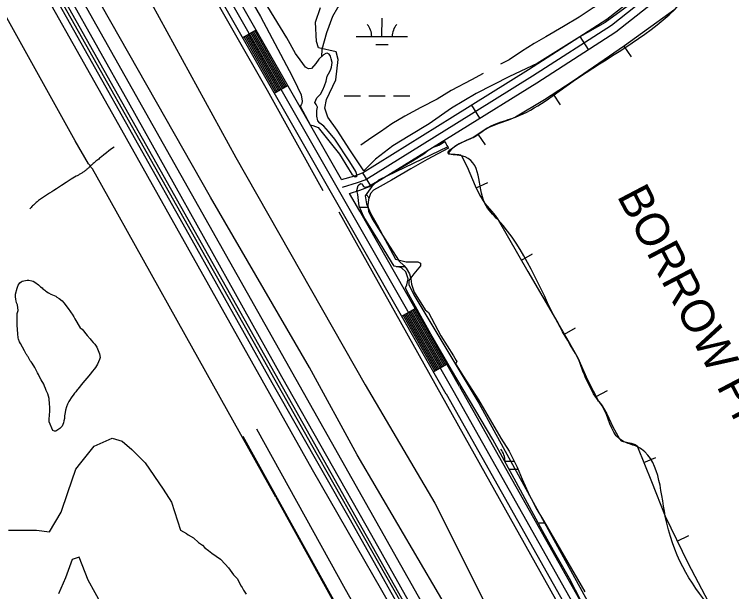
# Model space of a CAD drawing. Extents: x 3187622 to 3225504, y 800805 to 826213.
# Drawn here: x 3193075 to 3194473, y 822799 to 823924 of the extents above; entities that cross this region are included whole.
import ezdxf

# ---------------------------------------------------------------- set-up
doc = ezdxf.new("R2010")
doc.units = 0
for name, color, linetype in [('V-BORW-IDEN', 7, 'Continuous'), ('V-BORW-LINE', 7, 'Continuous'), ('V-LEVE-TOET', 7, 'Continuous'), ('V-RAIL-TRAK', 7, 'Continuous'), ('V-ROAD-CNTR', 7, 'Continuous'), ('V-SITE-VEGE', 7, 'Continuous'), ('V-SURV-LINE', 7, 'Continuous'), ('V-TOPO-SHOR', 7, 'Continuous'), ('V-WETL-SWMP', 7, 'Continuous')]:
    doc.layers.add(name, color=color, linetype=linetype)

msp = doc.modelspace()

# ---------------------------------------------------------------- linework, layer by layer
at = {"layer": 'V-BORW-LINE'}
for p, q in [((3194262.7, 823862), (3194276.9, 823841.4)), ((3194124.8, 823768.5), (3194138.4, 823747.5)), ((3193978.4, 823690.5), (3193992.4, 823669.9)), ((3193974.9, 823585.9), (3193997.5, 823596.6)), ((3194063, 823445.1), (3194084.6, 823457.6)), ((3194146.6, 823300.9), (3194168.2, 823313.5)), ((3194208.7, 823179.2), (3194230.8, 823191)), ((3194301.5, 823051.1), (3194324.6, 823060.5)), ((3194366.5, 822897.8), (3194389, 822908.7))]:
    msp.add_line(p, q, dxfattribs=at)
for points in [[(3194361.6, 823933.7), (3194263.6, 823862.7), (3194163.8, 823793.7), (3194108.1, 823757.7), (3194051.2, 823723.8), (3194037.9, 823717.6), (3194016.9, 823710.6), (3193996.4, 823702.4), (3193982.7, 823693.4), (3193969, 823684.2), (3193955.5, 823678), (3193941.7, 823672), (3193935.2, 823668), (3193926.4, 823660.6), (3193920.4, 823653.8), (3193920.1, 823653), (3193921, 823652.1), (3193933.9, 823651.9), (3193941.4, 823651.2), (3193944.3, 823650.2), (3193946.2, 823648.6), (3193957.6, 823626.9), (3193972.9, 823590.2), (3193981.5, 823572.1), (3193991.8, 823555.6), (3194005.1, 823539.8), (3194011.7, 823531.9), (3194017.5, 823523.4), (3194075.7, 823423.3), (3194133.8, 823323.1), (3194153.6, 823288.9), (3194173.2, 823254.5)], [(3194173.2, 823254.5), (3194191.4, 823211.7), (3194213.4, 823170.5), (3194216.8, 823165.7), (3194220.4, 823161), (3194229.5, 823145.4), (3194241, 823120.5), (3194253.9, 823096.6), (3194257.2, 823093.3), (3194261, 823091.5), (3194277.1, 823088.2), (3194284.4, 823085.8), (3194287.2, 823083.8), (3194289.3, 823081), (3194316.7, 823013.5), (3194343.3, 822945.9), (3194387, 822855.3), (3194433.8, 822766.2)]]:
    msp.add_lwpolyline(points, dxfattribs=at)
for points in [[(3194173.2, 823254.5), (3194133.8, 823323.1), (3194017.5, 823523.4), (3193991.8, 823555.6), (3193946.2, 823648.6), (3193920.4, 823653.8), (3193941.7, 823672), (3193969, 823684.2), (3193996.4, 823702.4), (3194051.2, 823723.8), (3194163.8, 823793.7), (3194361.6, 823933.7), (3194445, 824013.4), (3194502.9, 824036.7), (3194535.5, 824045.1), (3194547.6, 824055.8), (3194568.2, 824150.6), (3194657.5, 824394.2), (3194681.2, 824428.3)], [(3194746.7, 824428.2), (3194770.2, 824392.5), (3194839.9, 824358.9), (3194843.7, 824354.2), (3194822.9, 824352.6), (3194805.6, 824354.5), (3194783.8, 824344), (3194808, 824310.6), (3194860.9, 824111.5), (3194890.3, 824049), (3194919.9, 824022.8), (3194936.8, 823993.7), (3194967.5, 823945.1), (3194990.2, 823878.8), (3195044.4, 823786.8), (3195063.9, 823718), (3195053.2, 823688.8), (3195056.3, 823616.2), (3195008.6, 823396.2), (3194962.2, 823257.3), (3194949.6, 823254.7), (3194916.1, 823270.5), (3194892.6, 823394.4), (3194818.7, 823675.4), (3194764.8, 823725), (3194732.1, 823768.5), (3194627.7, 823861.2), (3194598.2, 823922.8), (3194572.9, 824011.1), (3194544.8, 824024.5), (3194532.2, 824018.4), (3194535.7, 823972.4), (3194544.3, 823935.6), (3194590.6, 823765.3), (3194640.4, 823657.8), (3194680.8, 823529.9), (3194719.1, 823459), (3194750.6, 823333.9), (3194793.9, 823142.5), (3194772.9, 823135.8), (3194752.4, 823099.7), (3194748.5, 823050.4), (3194776.1, 822932.3), (3194811.1, 822874.8), (3194830.8, 822797.1), (3194831.1, 822768.9), (3194796.7, 822656), (3194757.4, 822452), (3194745.4, 822448.1), (3194718.1, 822363.5), (3194698.9, 822349.8), (3194685.3, 822355.9), (3194657.8, 822398.5), (3194530.3, 822600.2), (3194494, 822692.8), (3194433.8, 822766.2), (3194343.3, 822945.9), (3194289.3, 823081), (3194253.9, 823096.6), (3194220.4, 823161), (3194213.4, 823170.5), (3194173.2, 823254.5)]]:
    msp.add_spline(points, degree=3, dxfattribs=at)
at = {"layer": 'V-LEVE-TOET'}
for points in [[(3193584.3, 822982.9), (3193407.8, 823299.3), (3193245.4, 823590.8), (3193227.2, 823623), (3193224.5, 823626.5), (3193223, 823629.3), (3193219.8, 823632.7), (3193193.4, 823677.9), (3193057.2, 823923.2), (3192861.4, 824271.3), (3192771.4, 824432.2)], [(3193069, 824431.6), (3193107.9, 824362.3), (3193312.3, 824000.4), (3193506.6, 823644.9), (3193758.4, 823202.4), (3193894.5, 822971.4)], [(3193584.3, 822982.9), (3193715.2, 822746.5), (3193715.3, 822746.3)], [(3193894.5, 822971.4), (3194028.2, 822704.5), (3194448.5, 821917.6)]]:
    msp.add_lwpolyline(points, dxfattribs=at)
at = {"layer": 'V-RAIL-TRAK'}
for points in [[(3193727.3, 822943), (3193577.7, 823206), (3193415.9, 823494.6), (3193219.9, 823842.7), (3193027.5, 824182.9), (3192887.4, 824431.9)], [(3194238.4, 822033.7), (3194009.1, 822443.2), (3193835.4, 822751.2), (3193727.3, 822943)]]:
    msp.add_lwpolyline(points, dxfattribs=at)
at = {"layer": 'V-ROAD-CNTR'}
for p, q in [((3193520, 823879), (3193546.1, 823893.9)), ((3194177, 823880.7), (3194193.2, 823855.4)), ((3193582, 823770.4), (3193608.1, 823785.3)), ((3193965.8, 823747.4), (3193981.6, 823721.9)), ((3193753.5, 823615.3), (3193769.3, 823589.9)), ((3193829.8, 823336.2), (3193855.9, 823351.1)), ((3193891.8, 823227.6), (3193917.8, 823242.5))]:
    msp.add_line(p, q, dxfattribs=at)
for points in [[(3193712.7, 823602), (3193738.4, 823609.7), (3193753.5, 823615.3), (3193928.5, 823724.2), (3194076.7, 823816.3), (3194229.7, 823914.5), (3194342.1, 824003.7), (3194404.7, 824048.8), (3194435.1, 824077.7), (3194479.6, 824135.2), (3194522.3, 824198.5), (3194552.2, 824257.2), (3194580, 824328.4), (3194616.3, 824418.1), (3194627.3, 824438.2)], [(3192892.8, 824434.6), (3193654.2, 823085.5)], [(3193916.6, 823184.2), (3193721.8, 823525.6), (3193306.3, 824253.5), (3193204.7, 824433.9)], [(3193222, 824433.9), (3193319.3, 824260.9), (3193734.8, 823533), (3193929.6, 823191.6)], [(3193712.7, 823602), (3193332.4, 824268.3), (3193239.2, 824433.9)], [(3194640.4, 824431), (3194629.9, 824411.7), (3194594, 824322.8), (3194565.9, 824251), (3194535.2, 824190.9), (3194491.7, 824126.4), (3194446.3, 824067.6), (3194414.3, 824037.3), (3194351.1, 823991.7), (3194238.4, 823902.3), (3194084.7, 823803.6), (3193936.4, 823711.5), (3193760.1, 823601.8), (3193743.1, 823595.5), (3193714.1, 823586.8)], [(3193728, 823575.3), (3193747.9, 823581.3), (3193766.8, 823588.3), (3193944.4, 823698.7), (3194092.7, 823790.9), (3194247.2, 823890.1), (3194360.2, 823979.8), (3194423.9, 824025.7), (3194457.4, 824057.5), (3194503.9, 824117.6), (3194548.1, 824183.3), (3194579.6, 824244.8), (3194607.9, 824317.3), (3194643.5, 824405.2), (3194653.6, 824423.8)], [(3193605.5, 823783.8), (3193543.5, 823892.4)], [(3193584.6, 823771.9), (3193522.7, 823880.5)], [(3193587.2, 823773.4), (3193525.3, 823882)], [(3193589.8, 823774.9), (3193527.9, 823883.5)], [(3193592.4, 823776.4), (3193530.5, 823884.9)], [(3193595, 823777.9), (3193533.1, 823886.4)], [(3193597.6, 823779.4), (3193535.7, 823887.9)], [(3193600.3, 823780.8), (3193538.3, 823889.4)], [(3193602.9, 823782.3), (3193540.9, 823890.9)], [(3193942.6, 823199), (3193747.9, 823540.4), (3193728, 823575.3)], [(3193912.6, 823239.5), (3193850.7, 823348.1)], [(3193915.2, 823241), (3193853.3, 823349.6)], [(3193894.4, 823229.1), (3193832.5, 823337.7)], [(3193897, 823230.6), (3193835.1, 823339.2)], [(3193899.6, 823232.1), (3193837.7, 823340.6)], [(3193902.2, 823233.6), (3193840.3, 823342.1)], [(3193904.8, 823235), (3193842.9, 823343.6)], [(3193907.4, 823236.5), (3193845.5, 823345.1)], [(3193910, 823238), (3193848.1, 823346.6)], [(3193942.7, 823199), (3195097.4, 821147.5)], [(3193916.5, 823184.3), (3195071.3, 821132.7)], [(3193929.6, 823191.6), (3195084.4, 821140.1)], [(3193546.7, 823116.4), (3193719.6, 822803.7), (3193783.2, 822690.8), (3193839.5, 822561.1), (3193931.2, 822385.2), (3194075.1, 822116.1), (3194127.2, 822033.7), (3194185.2, 821977.8), (3194639.7, 821147.1), (3195029.5, 820446.4), (3195072.9, 820348.7), (3195192.1, 820158.7), (3195238.4, 820041.1), (3195343.7, 819857.8), (3195584.5, 819427.5)], [(3193520.4, 823101.8), (3193693.4, 822789.1), (3193756.3, 822677.4), (3193812.4, 822548.2), (3193904.7, 822371.2), (3194049.2, 822101), (3194103.8, 822014.6), (3194161.1, 821959.4), (3194613.5, 821132.6), (3195002.6, 820433), (3195046.3, 820334.6), (3195165.2, 820145.1), (3195211.3, 820028), (3195317.6, 819843), (3195558.5, 819412.5)], [(3193654.2, 823085.5), (3194393.6, 821781.9), (3194932.5, 820818.5), (3195643.8, 819559.4), (3196039.6, 818863.6), (3196103.7, 818747.1), (3196200.1, 818577.4), (3196283.3, 818430.9), (3196415.9, 818198), (3196513.3, 818033.2), (3196633.1, 817833.5), (3197048.3, 817166.1), (3197473.1, 816486.2), (3198091.5, 815496.5), (3198625.8, 814645.6), (3198678.1, 814561.9), (3198728.8, 814484.2), (3198769.6, 814407.5), (3198909.8, 814179.8), (3198995, 814024.9)]]:
    msp.add_lwpolyline(points, dxfattribs=at)
at = {"layer": 'V-SITE-VEGE'}
for p, q in [((3193230.4, 823082.5), (3193265.7, 823098.5)), ((3193265.7, 823098.5), (3193285, 823092.1)), ((3193204.8, 823050.4), (3193230.4, 823082.5)), ((3193285, 823092.1), (3193304.3, 823076.1)), ((3193304.3, 823076.1), (3193329.9, 823050.4)), ((3193195.1, 823037.5), (3193204.8, 823050.4)), ((3193329.9, 823050.4), (3193365.2, 822999)), ((3193179.1, 822992.6), (3193195.1, 823037.5)), ((3193365.2, 822999), (3193381.3, 822973.3)), ((3193166.3, 822954.1), (3193179.1, 822992.6)), ((3193381.3, 822973.3), (3193399, 822918.7)), ((3193143.8, 822915.5), (3193166.3, 822954.1)), ((3193063.6, 822918.7), (3193082.8, 822918.7)), ((3193082.8, 822918.7), (3193118.1, 822918.7)), ((3193118.1, 822918.7), (3193143.8, 822915.5)), ((3193399, 822918.7), (3193404.4, 822915.5)), ((3193404.4, 822915.5), (3193410.7, 822912.2)), ((3193410.7, 822912.2), (3193413.8, 822909.8)), ((3193413.8, 822909.8), (3193423.9, 822904.1)), ((3193423.9, 822904.1), (3193434, 822895.2)), ((3193434, 822895.2), (3193441.8, 822889.6)), ((3193441.8, 822889.6), (3193446.5, 822884.8)), ((3193446.5, 822884.8), (3193453.5, 822879.1)), ((3193453.5, 822879.1), (3193459.7, 822874.3)), ((3193459.7, 822874.3), (3193476.8, 822862.1)), ((3193188, 822861.7), (3193174.6, 822826)), ((3193201.4, 822866.2), (3193188, 822861.7)), ((3193219.3, 822821.5), (3193201.4, 822866.2)), ((3193476.8, 822862.1), (3193486.1, 822852.5)), ((3193486.1, 822852.5), (3193492.3, 822845.3)), ((3193492.3, 822845.3), (3193502.3, 822831.7)), ((3193502.3, 822831.7), (3193509.3, 822824.5)), ((3193174.6, 822826), (3193161.2, 822794.7)), ((3193246.1, 822772.4), (3193219.3, 822821.5)), ((3193509.3, 822824.5), (3193516.9, 822810.1)), ((3193516.9, 822810.1), (3193519.2, 822806.9)), ((3193519.2, 822806.9), (3193521.5, 822802.2)), ((3193521.5, 822802.2), (3193526.9, 822794.2))]:
    msp.add_line(p, q, dxfattribs=at)
for points in [[(3193216.1, 823215.1), (3193212.4, 823210.3), (3193208.4, 823205.9), (3193199.1, 823193.7), (3193197.4, 823192.1), (3193195, 823188.5), (3193192.2, 823185.7), (3193189.7, 823182), (3193186.9, 823178.8), (3193181.6, 823169.9), (3193178.8, 823164.2), (3193176.7, 823159.4), (3193175.1, 823152.5), (3193173.9, 823148.1), (3193173.1, 823141.6), (3193172.6, 823136.3), (3193171.4, 823131.9), (3193171, 823127.8), (3193169.8, 823124.6), (3193168.2, 823121.4), (3193164.1, 823117.3), (3193160.1, 823114.5), (3193158, 823112.9), (3193156, 823111.7), (3193153.2, 823112.1), (3193149.9, 823113.3), (3193143.1, 823129.9), (3193143.1, 823135.2), (3193144.3, 823150.5), (3193144.4, 823159.4), (3193144, 823164.3), (3193142.8, 823175.6), (3193140.4, 823184.5), (3193137.5, 823191.4), (3193135.9, 823194.7), (3193133.9, 823199.5), (3193132.7, 823203.2), (3193127.5, 823211.7), (3193124.2, 823217.7), (3193122.2, 823222.2), (3193120.6, 823225.4), (3193117, 823231.9), (3193115, 823236), (3193109.7, 823244.1), (3193108.1, 823246.9), (3193106.1, 823248.9), (3193102.1, 823256.6), (3193100.8, 823258.3), (3193099.6, 823260.3), (3193098.4, 823261.9), (3193094.8, 823268.4), (3193087.1, 823282.6), (3193085.1, 823285.8), (3193083.1, 823291.1), (3193082.7, 823293.9), (3193081.9, 823301.2), (3193080.7, 823318.2), (3193080.7, 823329.9), (3193080.4, 823339.2), (3193080.8, 823341.2), (3193082.8, 823346.9), (3193081.2, 823357.8), (3193079.6, 823361.9), (3193078.8, 823365.5), (3193078, 823368.4), (3193077.2, 823374), (3193077.2, 823378.5), (3193080.9, 823390.6), (3193082.9, 823396.3), (3193084.9, 823399.1), (3193086.1, 823401.1), (3193088.6, 823403.1), (3193090.6, 823404.4), (3193099.9, 823406), (3193103.5, 823406), (3193109.2, 823405.1), (3193111.6, 823403.9), (3193115.3, 823401.9), (3193122.1, 823397), (3193126.2, 823393.4), (3193129.4, 823390.9), (3193131, 823389.3), (3193134.3, 823386.5), (3193136.3, 823384.8), (3193141.9, 823381.2), (3193146, 823378.8), (3193156.1, 823374.7), (3193158.1, 823373.1), (3193162.2, 823370.6), (3193168.2, 823365.8), (3193171.4, 823362.1), (3193180.3, 823350.8), (3193184.4, 823344.7), (3193185.6, 823342.7), (3193188, 823339.8), (3193190.8, 823334.6), (3193193.2, 823330.9), (3193203.7, 823313.5), (3193207, 823310.3), (3193217.1, 823298.5), (3193222.7, 823291.6)], [(3193222.7, 823291.6), (3193223.9, 823289.6), (3193228.8, 823284.7), (3193232, 823281.1), (3193235.6, 823275.8), (3193241.3, 823262.4), (3193242.1, 823255.6), (3193241.2, 823251.5), (3193239.2, 823246.7), (3193237.2, 823242.6), (3193233.5, 823235.8), (3193224.6, 823225.7), (3193223.4, 823223.6), (3193216.1, 823215.1)]]:
    msp.add_lwpolyline(points, dxfattribs=at)
at = {"layer": 'V-SURV-LINE'}
for points in [[(3193965.1, 822546.1), (3192901.9, 824431.9)], [(3192936.4, 824431.8), (3193991.3, 822560.8)]]:
    msp.add_lwpolyline(points, dxfattribs=at)
at = {"layer": 'V-TOPO-SHOR'}
for points in [[(3196669.7, 817789), (3196420.1, 818211.1), (3196348, 818329.5), (3196021.1, 818916.4), (3195920.7, 819106.9), (3195681.3, 819521.3), (3195459.9, 819917.7), (3195341.5, 820128.8), (3194986.3, 820754.3), (3194837, 821019.4), (3194610.5, 821418.4), (3194502.4, 821616.6), (3194445.8, 821717), (3194196.1, 822162.3), (3194075.1, 822368.2), (3193771.4, 822908.7), (3193596.3, 823217.6), (3193297.8, 823753), (3193179.4, 823964.1), (3192906.5, 824437.7)], [(3193189.6, 824437.7), (3193568, 823776.2), (3193676.1, 823580.6)], [(3192870.5, 824432.6), (3193272, 823719.6), (3193655.5, 823037.4), (3194095.7, 822270.4), (3194281, 821935.8), (3194281, 821921.4), (3194293.9, 821912.6), (3194523, 821505.9), (3194839.6, 820947.3), (3195012.1, 820643.6), (3195336.4, 820069.6), (3195480.5, 819812.2), (3195732.8, 819366.9)], [(3195107.3, 820738.8), (3195071.3, 820751.7), (3194754.7, 821292.3), (3194566.8, 821621.7), (3194288.8, 822113.4), (3194059.7, 822525.2), (3193743.1, 823065.8), (3193650.4, 823235.6), (3193457.3, 823567.7), (3193228.3, 823971.8), (3192963.1, 824435.1)], [(3193648.1, 823817.8), (3193642.1, 823821.2), (3193632.2, 823835.7), (3193622.7, 823847.9), (3193605.7, 823878.1), (3193569.1, 823938.7), (3193523.1, 824018), (3193465.9, 824122.3), (3193374.4, 824282.2), (3193290, 824431.1)], [(3193463.5, 824077.5), (3193554.4, 823920), (3193616.7, 823803.4), (3193627.1, 823782.1), (3193634.2, 823767.1), (3193636, 823755.2), (3193635.3, 823750.5), (3193633.7, 823747.5), (3193631.7, 823744.9), (3193651.7, 823708.9), (3193656.4, 823707.3), (3193667.1, 823703.8), (3193708.3, 823651.4), (3193726.1, 823623), (3193732.7, 823612.9), (3193738.9, 823607.4), (3193741.8, 823608.3), (3193742.9, 823609.6), (3193740.5, 823617.8), (3193728.7, 823636.8), (3193699.7, 823680.9), (3193687.2, 823695.7), (3193678.1, 823706.1), (3193670.5, 823711.8), (3193666.5, 823716.8), (3193664.4, 823725.6), (3193664.2, 823736.8), (3193666, 823743), (3193662.9, 823748.5), (3193660.5, 823752.4), (3193664.6, 823761.7), (3193671.4, 823768.7), (3193676.3, 823777.1), (3193679.4, 823784.7), (3193682.7, 823794), (3193684.3, 823803.9), (3193689.5, 823812.8), (3193691.8, 823817.5), (3193693.3, 823821.4), (3193694.3, 823830.4), (3193692.7, 823837.2), (3193691.1, 823842.6), (3193688.8, 823846.5), (3193684.9, 823848.4), (3193681.8, 823848.1), (3193677.6, 823845.5), (3193668.1, 823836.8), (3193662.4, 823828.2), (3193654.1, 823818.7), (3193648.1, 823817.8)], [(3193674.1, 823841.6), (3193675.1, 823856.1), (3193683.7, 823889), (3193695.5, 823920.6), (3193705.4, 823937.3), (3193717.7, 823954.1), (3193723.3, 823971.2), (3193735.2, 823990.1), (3193748.9, 824002), (3193760.1, 824016.6)], [(3194271, 823986.6), (3194246.8, 823966.2), (3194225, 823949), (3194203, 823936.5), (3194175.7, 823918.6), (3194144.8, 823900.2), (3194110.8, 823880.3), (3194087.8, 823867), (3194063, 823851.8)], [(3194063, 823851.8), (3194039.2, 823835.7), (3194022.2, 823826.7)], [(3193988.3, 823808.8), (3193965.5, 823796.8), (3193926.1, 823775.4), (3193899, 823758.8), (3193867.1, 823742.7), (3193835.8, 823725.4), (3193810.3, 823710.5), (3193788.5, 823695), (3193771.8, 823684.3), (3193750, 823669.3)], [(3193269.4, 823665.5), (3193264.4, 823661.9), (3193259.4, 823658.2), (3193254.5, 823654.5), (3193249.7, 823650.6), (3193244.9, 823646.7), (3193243.1, 823645.2), (3193243.1, 823645.2), (3193241.3, 823643.7), (3193239.5, 823642.2), (3193237.7, 823640.7), (3193235.9, 823639.3), (3193234.1, 823637.8), (3193232.3, 823636.3), (3193230.5, 823634.8), (3193228.7, 823633.2), (3193227, 823631.7), (3193225.2, 823630.2), (3193223.5, 823628.7), (3193223.4, 823628.6), (3193223.4, 823628.6), (3193222.3, 823627.5), (3193221.2, 823626.4), (3193220.1, 823625.3), (3193219, 823624.3), (3193217.8, 823623.3), (3193216.7, 823622.2), (3193215.5, 823621.2), (3193214.3, 823620.3), (3193213.1, 823619.3), (3193211.8, 823618.4), (3193210.6, 823617.5), (3193209.3, 823616.6), (3193208.1, 823615.7), (3193206.8, 823614.9), (3193205.5, 823614), (3193204.1, 823613.2), (3193202.8, 823612.5), (3193201.5, 823611.7), (3193200.1, 823611), (3193198.7, 823610.3), (3193197.3, 823609.6), (3193195.9, 823608.9), (3193195.7, 823608.8), (3193195.7, 823608.8), (3193186, 823602.7), (3193176.4, 823596.6), (3193166.8, 823590.4), (3193157.2, 823584.1), (3193152.2, 823580.8), (3193148.1, 823578.3), (3193144, 823575.8), (3193139.9, 823573.2), (3193135.8, 823570.6), (3193131.8, 823567.9), (3193127.9, 823565.1), (3193124.1, 823562.5), (3193124.1, 823562.5), (3193122.5, 823561.3), (3193121, 823560.1), (3193119.5, 823558.8), (3193118, 823557.6), (3193116.5, 823556.3), (3193115, 823554.9), (3193113.6, 823553.6), (3193112.2, 823552.2), (3193110.8, 823550.8), (3193109.5, 823549.4), (3193108.1, 823547.9), (3193106.8, 823546.5), (3193105.7, 823545.2)], [(3193919.5, 823665.7), (3193784.3, 823601.2), (3193771.4, 823588.3), (3193758.5, 823570.3), (3193761.1, 823554.8), (3193768.8, 823536.8), (3193781.7, 823513.6), (3193817.7, 823446.7), (3193838.3, 823441.6), (3193848.6, 823441.6), (3193861.5, 823441.6), (3193866.6, 823439), (3193866.6, 823433.9), (3193853.7, 823418.4), (3193843.5, 823405.5), (3193843.5, 823397.8), (3193853.7, 823377.2), (3193979.9, 823166.2), (3194268.2, 822641), (3194458.6, 822311.6), (3194777.8, 821742.7), (3194960.6, 821415.8), (3195056.3, 821245.3)], [(3193707, 823539.4), (3193961.9, 823083.8), (3194227, 822610.2), (3194435.5, 822249.8), (3194790.7, 821608.9), (3194893.7, 821433.8), (3195158.8, 820973.1)]]:
    msp.add_lwpolyline(points, dxfattribs=at)
at = {"layer": 'V-WETL-SWMP'}
for p, q in [((3193661.9, 823908.7), (3193671.5, 823937.4)), ((3194271.4, 823941.4), (3194226, 823907.9)), ((3193663.5, 823871.4), (3193661.9, 823908.7)), ((3193791.4, 823880.9), (3193791.5, 823916.9)), ((3194226, 823907.9), (3194177, 823880.1)), ((3193741.4, 823881), (3193841.4, 823880.8)), ((3194177, 823880.1), (3194093.9, 823828)), ((3193667.8, 823858.7), (3193663.5, 823871.4)), ((3193779.4, 823865.5), (3193803.4, 823865.4)), ((3193702.2, 823850.8), (3193667.8, 823858.7)), ((3193706, 823836.1), (3193702.2, 823850.8)), ((3193701.4, 823796.3), (3193706, 823836.1)), ((3194093.9, 823828), (3194040, 823803)), ((3193683.5, 823758), (3193701.4, 823796.3)), ((3194040, 823803), (3193974.7, 823769.6)), ((3193974.7, 823769.6), (3193926.8, 823741.4)), ((3193680, 823741.4), (3193683.5, 823758)), ((3193717.7, 823765.6), (3193749.7, 823765.5)), ((3193765.7, 823765.5), (3193797.7, 823765.4)), ((3193813.7, 823765.4), (3193845.7, 823765.3)), ((3193685.9, 823723.8), (3193680, 823741.4)), ((3193926.8, 823741.4), (3193883.4, 823711)), ((3193704.2, 823698.3), (3193685.9, 823723.8)), ((3193883.4, 823711), (3193845.9, 823687.8)), ((3193728.6, 823660.2), (3193704.2, 823698.3)), ((3193845.9, 823687.8), (3193812.4, 823667.6)), ((3193756.1, 823619.1), (3193728.6, 823660.2)), ((3193812.4, 823667.6), (3193778.7, 823641.9)), ((3193778.7, 823641.9), (3193756.1, 823619.1)), ((3193747.9, 823548.3), (3193764.2, 823548.3)), ((3193818.9, 823432.7), (3193836.1, 823432.7)), ((3194030.6, 823053.2), (3194048.8, 823053.1)), ((3194039.1, 823037.7), (3194056.3, 823037.7)), ((3194095.8, 822933), (3194108.7, 822932.9))]:
    msp.add_line(p, q, dxfattribs=at)
for points in [[(3194125.3, 822879.3), (3194104.3, 822917.4), (3194083.4, 822955.8), (3194053, 823012.4), (3194007.3, 823095.6), (3193927.1, 823231.6), (3193886.6, 823300.6), (3193840.6, 823383.9), (3193837.1, 823391.2), (3193840, 823396.7), (3193842.5, 823408.6), (3193837.8, 823422.1), (3193829.2, 823430.2), (3193821.6, 823432), (3193815.2, 823433.6), (3193788.7, 823476.8), (3193755.8, 823529.8), (3193747.2, 823550), (3193745.8, 823561.3), (3193744.3, 823572.9), (3193742.7, 823580.7), (3193745.2, 823590.6), (3193749.6, 823594.5), (3193752.2, 823593.8), (3193755.1, 823588.6), (3193758.2, 823587), (3193764.5, 823588.3), (3193805.3, 823612.1), (3193850.7, 823638.8), (3193872.7, 823652.4), (3193881.3, 823659.7), (3193890.1, 823664.7), (3193902.4, 823669.4), (3193914.1, 823676.4), (3193914.2, 823675.4), (3193915.7, 823672.7), (3193917.9, 823668.6), (3193919.5, 823665.7), (3193921.1, 823663.3)], [(3193921.1, 823663.3), (3193879.1, 823641), (3193847.7, 823623.1), (3193810.2, 823601.1), (3193787.7, 823588.5), (3193774.7, 823581.2), (3193768.8, 823574.7), (3193764.9, 823563.5), (3193763.8, 823552.5), (3193764.9, 823540.6), (3193772.5, 823525.5), (3193801.5, 823479.6), (3193824.7, 823443), (3193834.2, 823434.8), (3193838.8, 823429.6), (3193844.8, 823418.4), (3193847.5, 823408.8), (3193848.8, 823398.6), (3193853.8, 823382.8), (3193875.3, 823348.6), (3193882, 823343.1), (3193905.9, 823297.6), (3193930.7, 823258.5), (3193936.1, 823249.4), (3193936.9, 823247.3), (3193934.9, 823242.9), (3193937.5, 823239.2), (3193950, 823218.5), (3193979.2, 823173.1), (3194022.7, 823098), (3194038.9, 823072.6), (3194054.6, 823041.5), (3194064.7, 823018.1), (3194076, 822992.3), (3194091.2, 822962.3), (3194105.9, 822937.6), (3194186.7, 822798.7)], [(3194179.4, 822780.3), (3194156.6, 822824.8), (3194125.3, 822879.3)]]:
    msp.add_lwpolyline(points, dxfattribs=at)
for centre, start, end in [((3193736.1, 823881.5), 359.1115, 40.6551), ((3193846.6, 823881.2), 139.1115, 180.6551), ((3193735.4, 823548.8), 30.0578, 40.6551), ((3193995.9, 823053.7), 359.1115, 40.6551)]:
    msp.add_arc(centre, 35.2, start, end, dxfattribs=at)

# ---------------------------------------------------------------- texts
at = {"layer": 'V-BORW-IDEN'}
msp.add_text('BORROW PIT', height=64, rotation=297.646, dxfattribs=at).set_placement((3194248.2, 823570.2))

doc.saveas('drawing.dxf')
